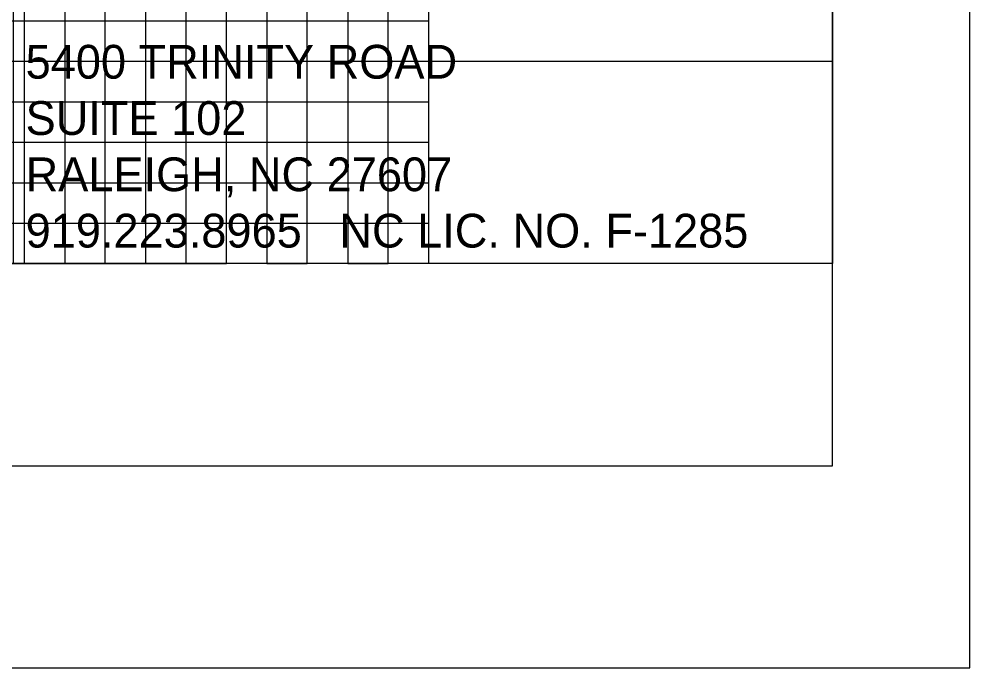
# Model space of a CAD drawing. Extents: x 1524869 to 1526553, y 501099 to 502199.
# Drawn here: x 1526435.4 to 1526553.1, y 501098.6 to 501178.8 of the extents above; entities that cross this region are included whole.
import ezdxf

# ---------------------------------------------------------------- set-up
doc = ezdxf.new("R2010")
doc.units = 0
for name, color, linetype in [('Prop Grid Mask', 7, 'Continuous'), ('Prop Horizontal Alignment Curve and Spiral Data', 7, 'Continuous'), ('Sheet Layout Profile Border Port 1', 7, 'Continuous'), ('Sheet Plot Border Outside CELL', 7, 'Continuous'), ('Sheet Profile CELL', 7, 'Continuous'), ('Sheet Profile Grid Major CELL', 7, 'Continuous'), ('Sheet Profile Grid Middle CELL', 7, 'Continuous'), ('Sheet Profile Grid Minor CELL', 7, 'Continuous')]:
    doc.layers.add(name, color=color, linetype=linetype)

msp = doc.modelspace()

# ---------------------------------------------------------------- linework, layer by layer
at = {"layer": 'Prop Grid Mask'}
msp.add_lwpolyline([(1526434.75, 501200.68), (1526536.08, 501200.68), (1526536.08, 501148.56), (1526434.75, 501148.56)], close=True, dxfattribs=at)
at = {"layer": 'Sheet Layout Profile Border Port 1'}
msp.add_lwpolyline([(1525536.08, 501648.56), (1526486.08, 501648.56), (1526486.08, 501148.56), (1525536.08, 501148.56)], close=True, dxfattribs=at)
at = {"layer": 'Sheet Plot Border Outside CELL'}
msp.add_lwpolyline([(1524869.08, 501098.56), (1526553.08, 501098.56), (1526553.08, 502198.56), (1524869.08, 502198.56)], close=True, dxfattribs=at)
at = {"layer": 'Sheet Profile CELL'}
for p, q in [((1526536.08, 501148.56), (1525036.08, 501148.56)), ((1525036.08, 501123.56), (1526536.08, 501123.56))]:
    msp.add_line(p, q, dxfattribs=at)
msp.add_lwpolyline([(1526536.08, 502173.56), (1525036.08, 502173.56), (1525036.08, 501123.56), (1526536.08, 501123.56)], close=True, dxfattribs=at)
at = {"layer": 'Sheet Profile Grid Major CELL'}
msp.add_line((1526436.08, 501148.56), (1526436.08, 501148.56), dxfattribs=at)
for points in [[(1525986.08, 501148.56), (1526036.08, 501148.56), (1526036.08, 501648.56), (1526086.08, 501648.56), (1526086.08, 501148.56), (1526136.08, 501148.56), (1526136.08, 501648.56), (1526186.08, 501648.56), (1526186.08, 501148.56), (1526236.08, 501148.56), (1526236.08, 501648.56), (1526286.08, 501648.56), (1526286.08, 501148.56), (1526336.08, 501148.56), (1526336.08, 501648.56), (1526386.08, 501648.56), (1526386.08, 501148.56), (1526436.08, 501148.56), (1526436.08, 501148.56), (1526436.08, 501648.56), (1526486.08, 501648.56), (1526486.08, 501148.56)], [(1526536.08, 501148.56), (1525036.08, 501148.56)]]:
    msp.add_lwpolyline(points, dxfattribs=at)
at = {"layer": 'Sheet Profile Grid Middle CELL'}
for points in [[(1526011.08, 501148.56), (1526061.08, 501148.56), (1526061.08, 501648.56), (1526111.08, 501648.56), (1526111.08, 501148.56), (1526161.08, 501148.56), (1526161.08, 501648.56), (1526211.08, 501648.56), (1526211.08, 501148.56), (1526261.08, 501148.56), (1526261.08, 501648.56), (1526311.08, 501648.56), (1526311.08, 501148.56), (1526361.08, 501148.56), (1526361.08, 501648.56), (1526411.08, 501648.56), (1526411.08, 501148.56), (1526461.08, 501148.56), (1526461.08, 501648.56)], [(1526536.08, 501173.56), (1525036.08, 501173.56)]]:
    msp.add_lwpolyline(points, dxfattribs=at)
at = {"layer": 'Sheet Profile Grid Minor CELL'}
for p, q in [((1526486.08, 501178.56), (1526036.08, 501178.56)), ((1526036.08, 501168.56), (1526486.08, 501168.56)), ((1526486.08, 501163.56), (1526036.08, 501163.56)), ((1526036.08, 501158.56), (1526486.08, 501158.56)), ((1526036.08, 501153.56), (1526486.08, 501153.56)), ((1526486.08, 501153.56), (1526486.08, 501153.56))]:
    msp.add_line(p, q, dxfattribs=at)
for points in [[(1526441.08, 501648.56), (1526441.08, 501148.56), (1526446.08, 501148.56), (1526446.08, 501648.56)], [(1526451.08, 501648.56), (1526451.08, 501148.56), (1526456.08, 501148.56), (1526456.08, 501648.56)], [(1526466.08, 501648.56), (1526466.08, 501148.56), (1526471.08, 501148.56), (1526471.08, 501648.56)], [(1526476.08, 501648.56), (1526476.08, 501148.56), (1526481.08, 501148.56), (1526481.08, 501648.56)]]:
    msp.add_lwpolyline(points, dxfattribs=at)

# ---------------------------------------------------------------- texts
at = {"layer": 'Prop Horizontal Alignment Curve and Spiral Data'}
for s, height, p in [('5400 TRINITY ROAD', 4.1773, (1526436.23, 501171.44)), ('SUITE 102', 4.177, (1526436.23, 501164.48)), ('RALEIGH, NC 27607', 4.1773, (1526436.23, 501157.52)), ('919.223.8965   NC LIC. NO. F-1285', 4.1773, (1526436.23, 501150.55))]:
    msp.add_text(s, height=height, rotation=360, dxfattribs=at).set_placement(p)

doc.saveas('drawing.dxf')
